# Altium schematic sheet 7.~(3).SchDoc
size 609 x 444 mm
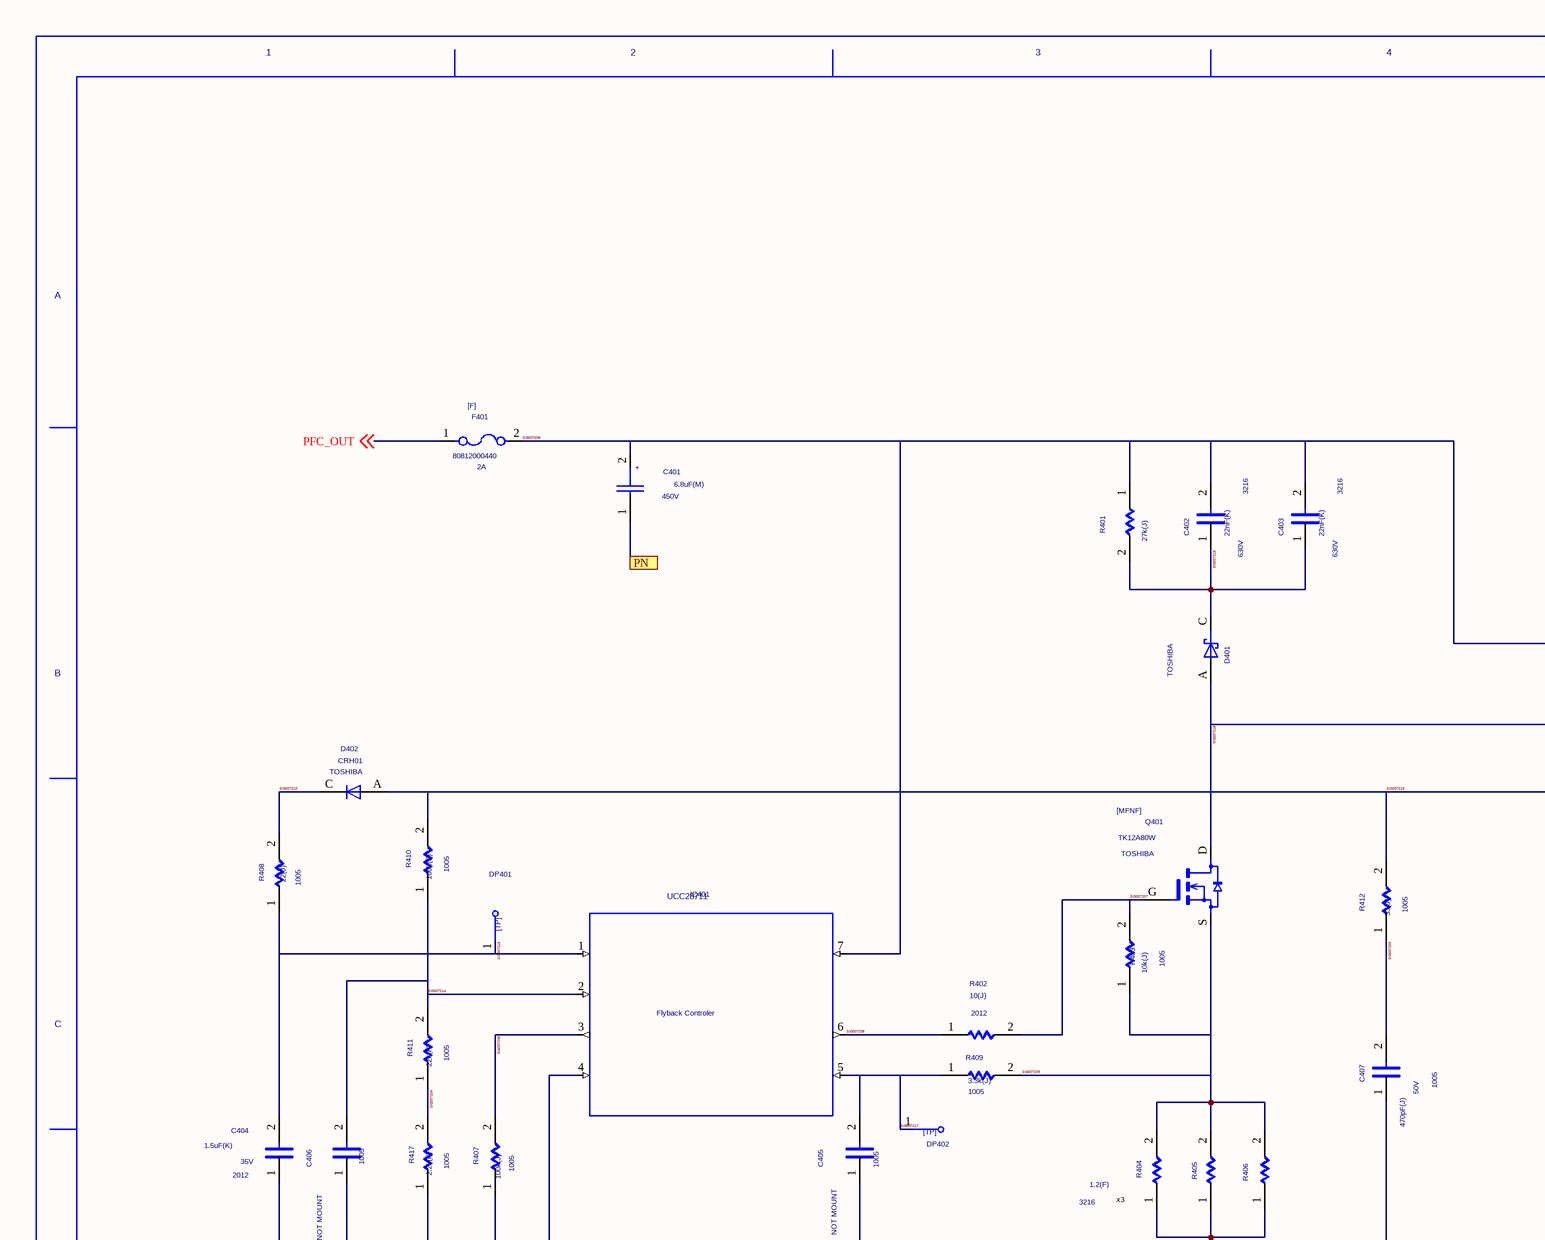
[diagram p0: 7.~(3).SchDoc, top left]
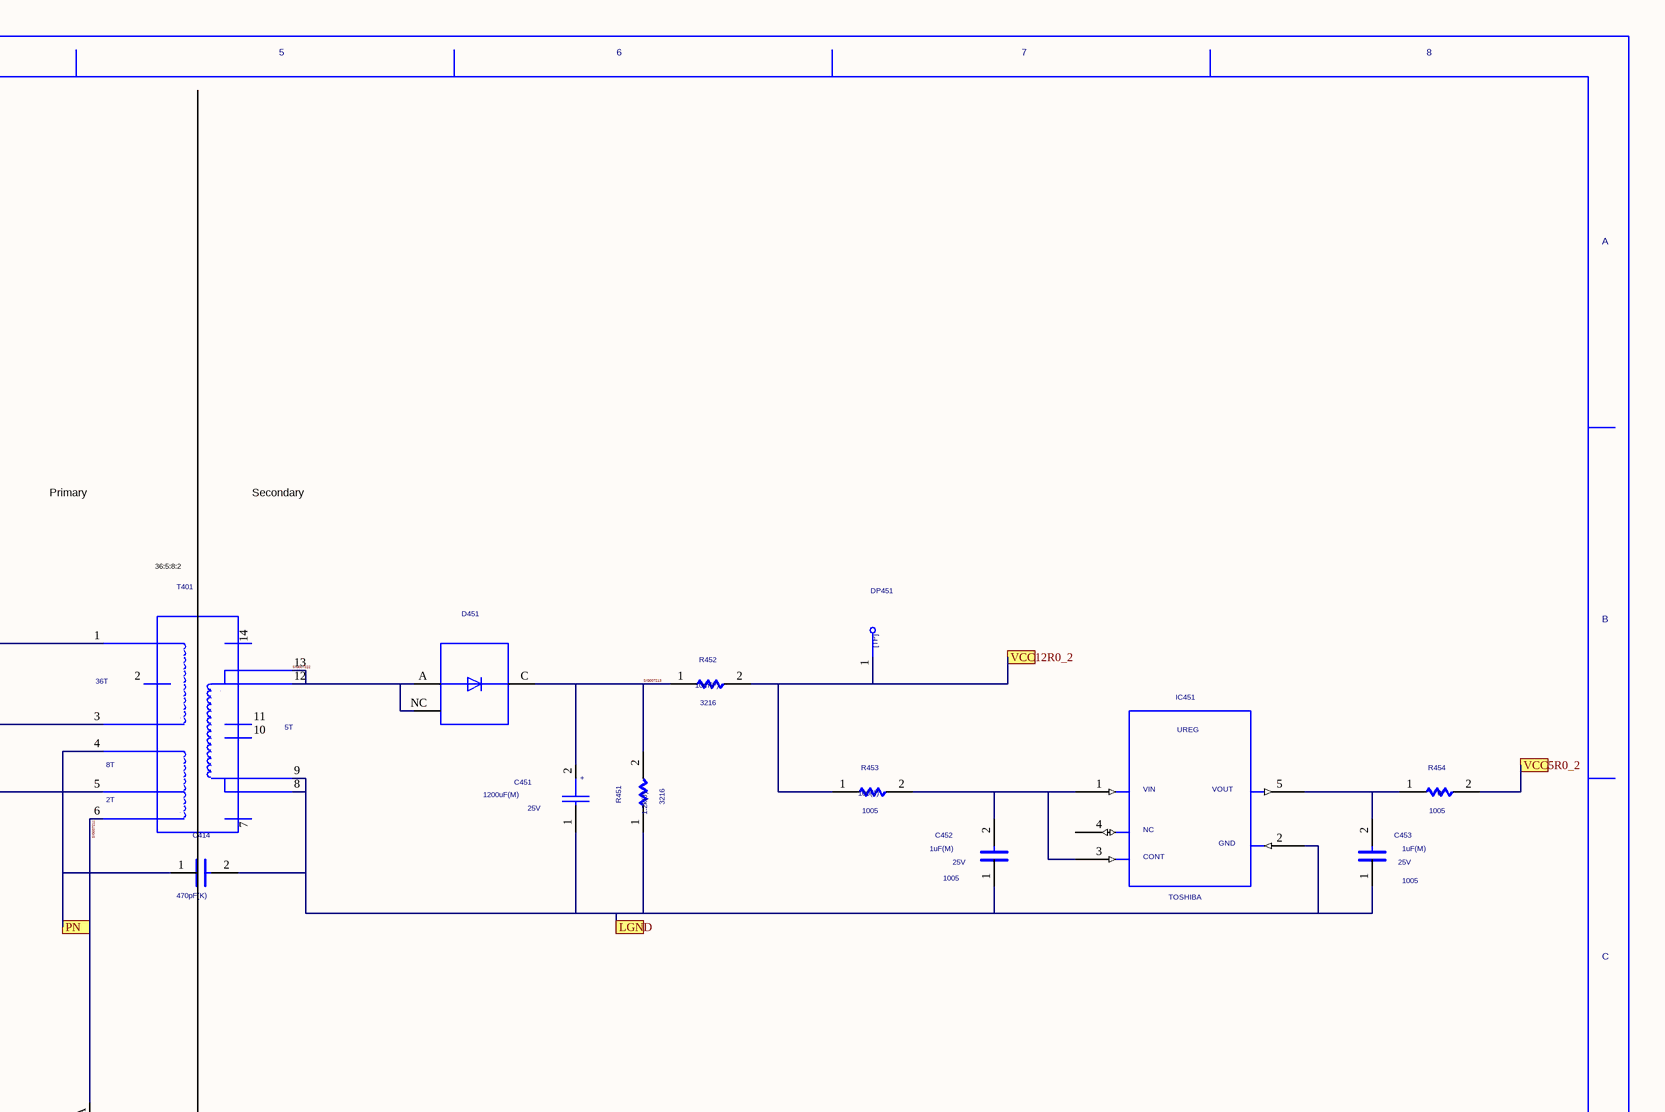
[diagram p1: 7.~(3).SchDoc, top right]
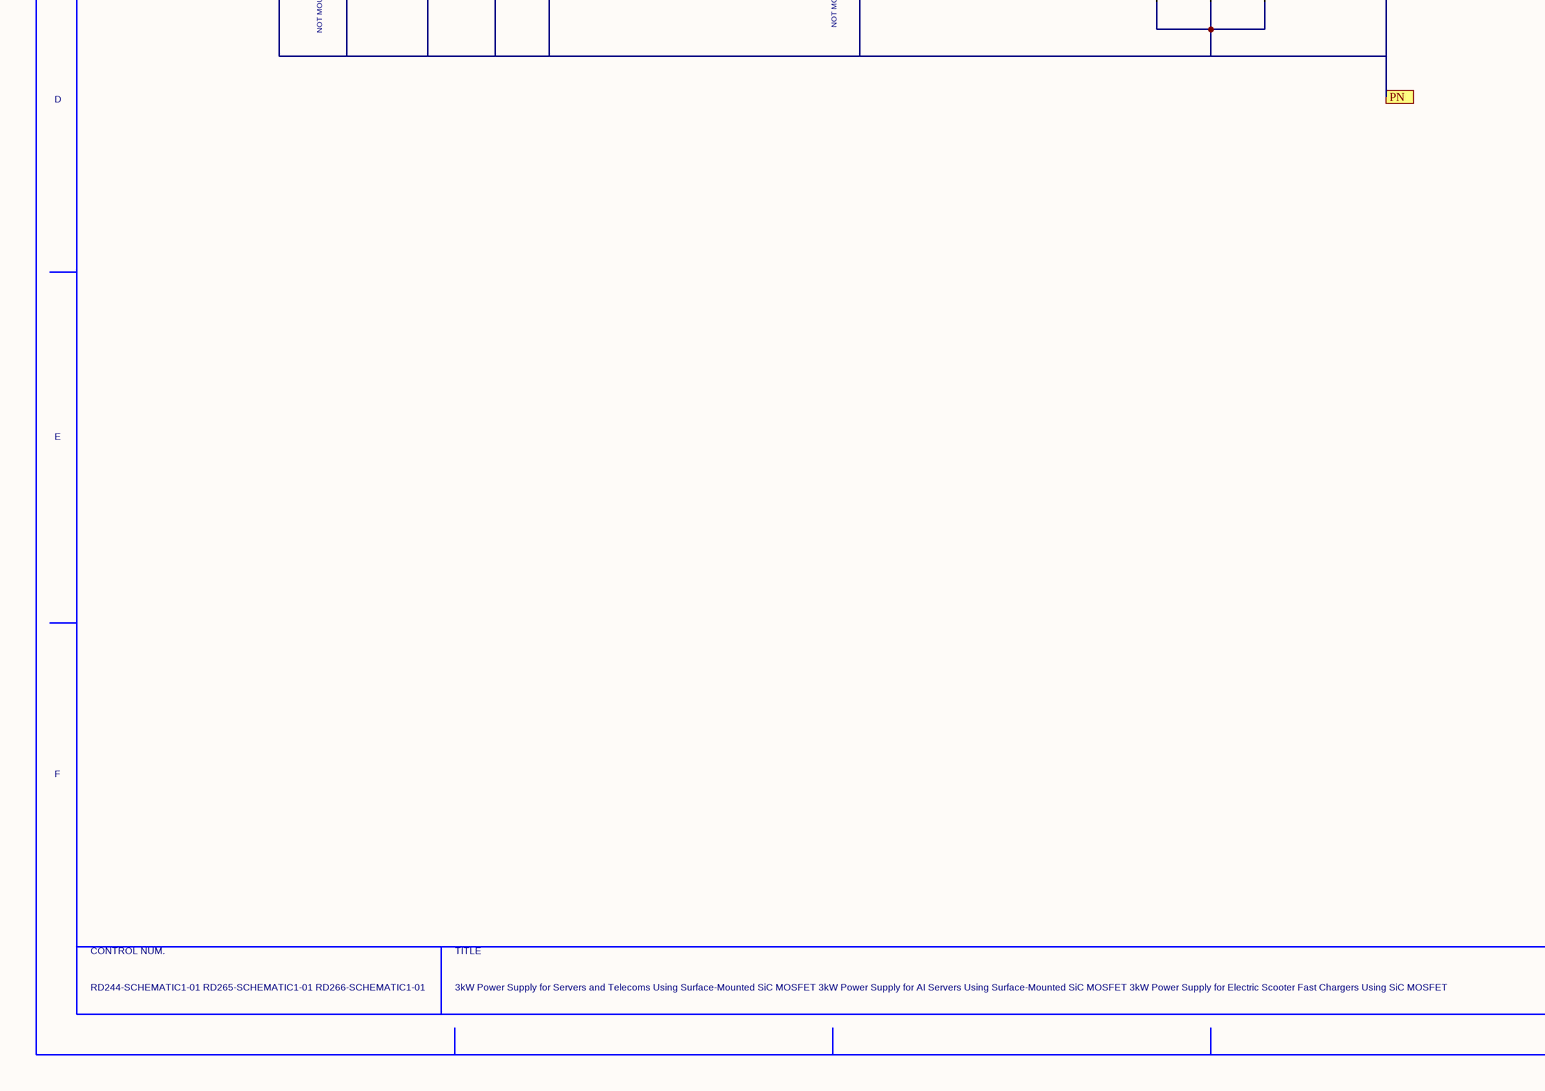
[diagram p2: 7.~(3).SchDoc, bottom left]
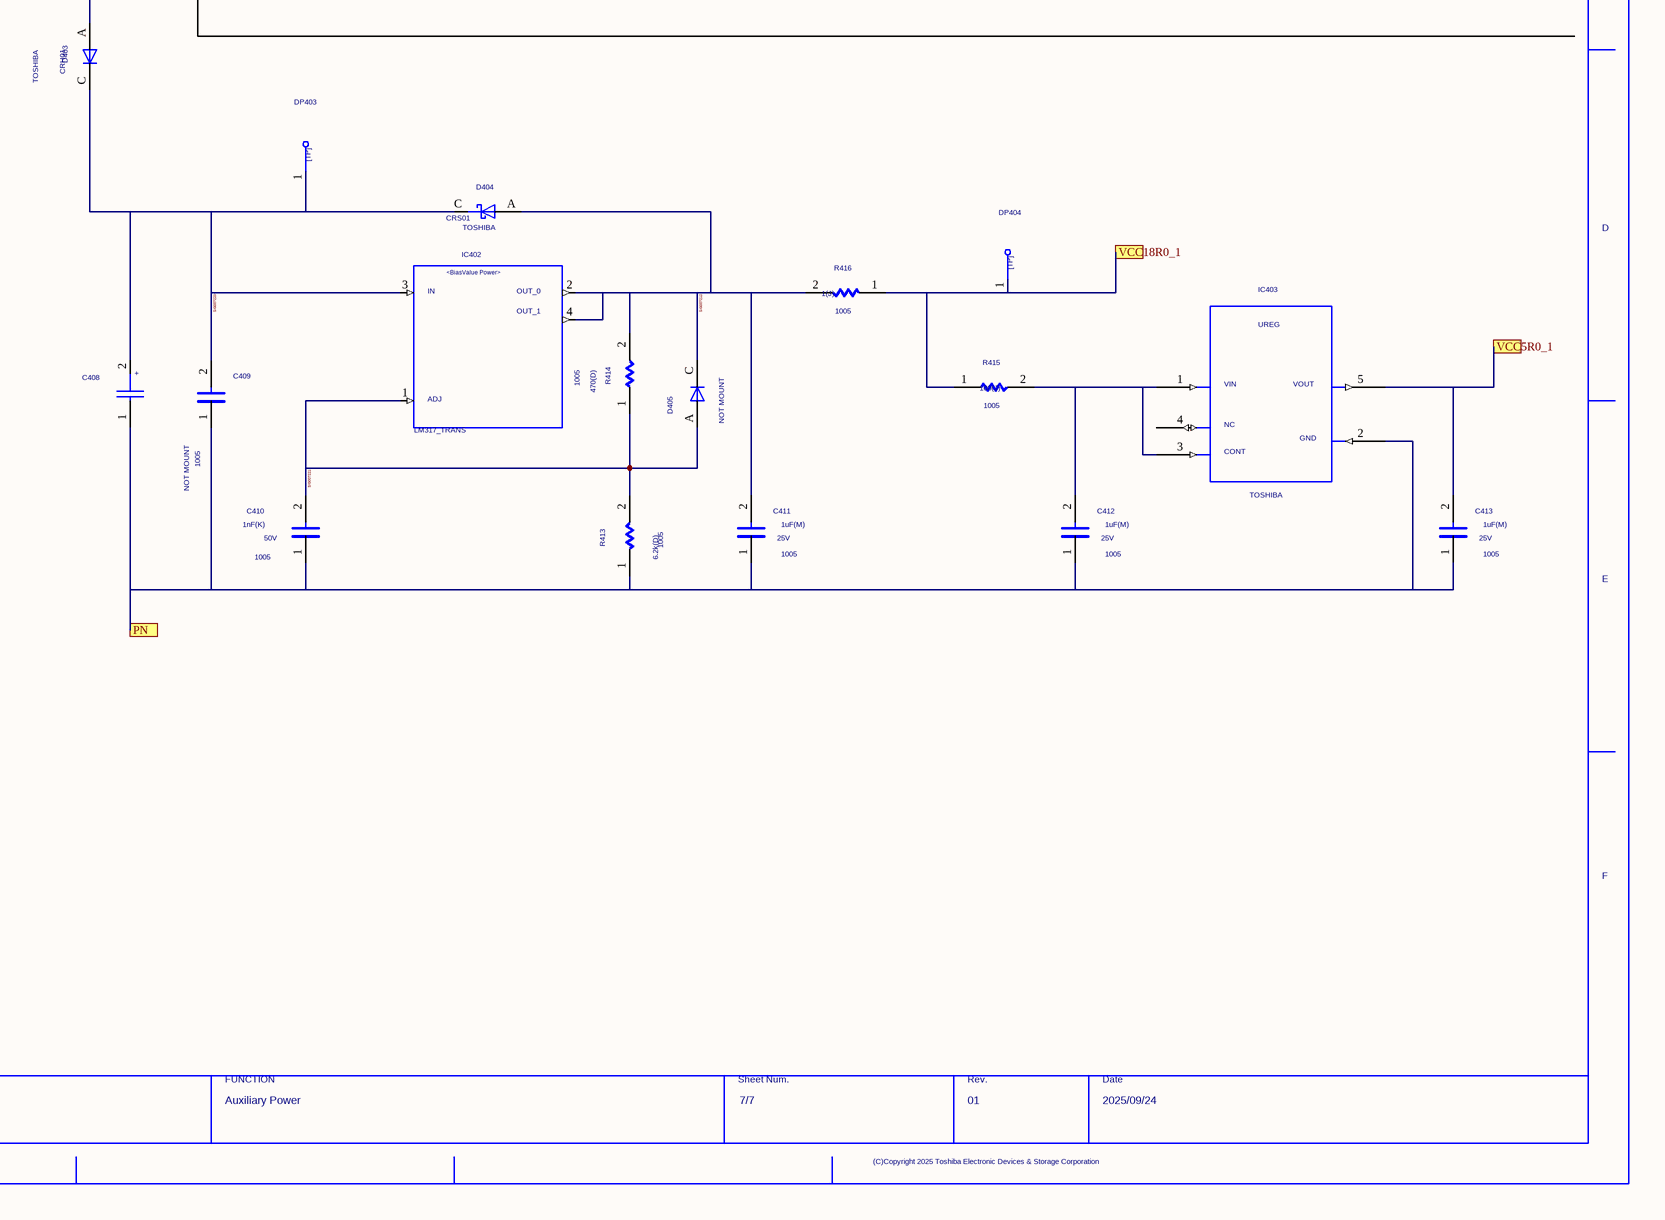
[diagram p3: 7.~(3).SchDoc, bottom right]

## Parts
C401  VAL1: 6.8uF(M)  VAL2: 450V  (hidden comment: CP)
C402  VAL1: 22nF(K)  VAL2: 630V  SIZECODESMD: 3216  (hidden comment: C)
C403  VAL1: 22nF(K)  VAL2: 630V  SIZECODESMD: 3216  (hidden comment: C)
C404  VAL1: 1.5uF(K)  VAL2: 35V  SIZECODESMD: 2012  (hidden comment: GRM21BC71E106KE01)
C405  NOTMOUNT: NOT MOUNT  SIZECODESMD: 1005  (hidden comment: C)
C406  NOTMOUNT: NOT MOUNT  SIZECODESMD: 1005  (hidden comment: C)
C407  VAL1: 470pF(J)  VAL2: 50V  SIZECODESMD: 1005  (hidden comment: C)
C408  EMLA350ARA331MJA0G  (value not drawn)
C409  NOTMOUNT: NOT MOUNT  SIZECODESMD: 1005  (hidden comment: C)
C410  VAL1: 1nF(K)  VAL2: 50V  SIZECODESMD: 1005  (hidden comment: C)
C411  VAL1: 1uF(M)  VAL2: 25V  SIZECODESMD: 1005  (hidden comment: C)
C412  VAL1: 1uF(M)  VAL2: 25V  SIZECODESMD: 1005  (hidden comment: C)
C413  VAL1: 1uF(M)  VAL2: 25V  SIZECODESMD: 1005  (hidden comment: C)
C414  USERCOMPTEXT1: 470pF(K)  (hidden comment: DE2B3SA221KA3BT02F)
C451  VAL1: 1200uF(M)  VAL2: 25V  (hidden comment: CP)
C452  VAL1: 1uF(M)  VAL2: 25V  SIZECODESMD: 1005  (hidden comment: C)
C453  VAL1: 1uF(M)  VAL2: 25V  SIZECODESMD: 1005  (hidden comment: C)
D401  USERCOMPTEXT3: TOSHIBA  (hidden comment: CRF03A)
D402  VAL1: CRH01  USERCOMPTEXT3: TOSHIBA  (hidden comment: D)
D403  VAL1: CRH01  USERCOMPTEXT3: TOSHIBA  (hidden comment: D)
D404  VAL1: CRS01  USERCOMPTEXT3: TOSHIBA  (hidden comment: SBD)
D405  NOTMOUNT: NOT MOUNT  (hidden comment: D)
D451  RF501BGE2S  (value not drawn)
DP401  TP  (value not drawn)
DP402  TP  (value not drawn)
DP403  TP  (value not drawn)
DP404  TP  (value not drawn)
DP451  TP  (value not drawn)
F401  VAL1: 2A  VAL3: 80812000440  (hidden comment: F)
IC401  UCC28711
IC402  LM317_TRANS  [DCY0004A_N]
IC403  USERCOMPTEXT3: TOSHIBA  (hidden comment: TCR1HF50B)
IC451  USERCOMPTEXT3: TOSHIBA  (hidden comment: TCR1HF50B)
Q401  USERCOMPTEXT3: TOSHIBA  VAL3: TK12A80W  (hidden comment: MFNF)
R401  VAL1: 27k(J)  (hidden comment: R)
R402  VAL1: 10(J)  SIZECODESMD: 2012  (hidden comment: R)
R403  VAL1: 10k(J)  SIZECODESMD: 1005  (hidden comment: R)
R404  VAL1: 1.2(F)  SIZECODESMD: 3216  (hidden comment: R)
R405  R  (value not drawn)
R406  R  (value not drawn)
R407  VAL1: 100k(J)  SIZECODESMD: 1005  (hidden comment: R)
R408  VAL1: 22(J)  SIZECODESMD: 1005  (hidden comment: R)
R409  VAL1: 3.3k(J)  SIZECODESMD: 1005  (hidden comment: R)
R410  VAL1: 100k(F)  SIZECODESMD: 1005  (hidden comment: R)
R411  VAL1: 22k(F)  SIZECODESMD: 1005  (hidden comment: R)
R412  VAL1: 33(J)  SIZECODESMD: 1005  (hidden comment: R)
R413  VAL1: 6.2k(D)  SIZECODESMD: 1005  (hidden comment: R)
R414  VAL1: 470(D)  SIZECODESMD: 1005  (hidden comment: R)
R415  VAL1: 100(J)  SIZECODESMD: 1005  (hidden comment: R)
R416  VAL1: 1(J)  SIZECODESMD: 1005  (hidden comment: R)
R417  VAL1: 2.2k(F)  SIZECODESMD: 1005  (hidden comment: R)
R451  VAL1: 1.2k(J)  SIZECODESMD: 3216  (hidden comment: R)
R452  VAL1: 10m(F)  SIZECODESMD: 3216  (hidden comment: R)
R453  VAL1: 100(J)  SIZECODESMD: 1005  (hidden comment: R)
R454  VAL1: 0  SIZECODESMD: 1005  (hidden comment: R)
T401  T3_12V67A  (value not drawn)
U?  DATE: 2025/09/24  DRAWINGNUMBER: RD244-SCHEMATIC1-01 / RD265-SCHEMATIC1-01 / RD266-SCHEMATIC1-01  TITLE: 3kW Power Supply for Servers and Telecoms Using Surface-Mounted SiC MOSFET / 3kW Power Supply for AI Servers Using Surface-Mounted SiC MOSFET / 3kW Power Supply for Electric Scooter Fast Chargers Using SiC MOSFET  FUNCTION: Auxiliary Power  SHEETNUMBER: 7/7  REVISION: 01  (hidden comment: WAKU_DEF_A3_1)

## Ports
LGND, PN, VCC5R0_1, VCC5R0_2, VCC12R0_2, VCC18R0_1

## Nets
LGND: C414.2 C451.1 C452.1 C453.1 IC451.2 R451.1 T401.8 T401.9 ; port LGND
PFC_OUT: F401.1 ; off-sheet PFC_OUT
SIG007201: C453.2 IC451.5 R454.1
SIG007202: C452.2 IC451.1 IC451.3 R453.2
SIG007203: C407.2 R412.1
SIG007204: R411.1 R417.2
SIG007205: IC401.3 R407.2
SIG007206: C401.2 C402.2 C403.2 F401.2 IC401.7 R401.1 T401.1
SIG007207: Q401.G R402.2 R403.2
SIG007208: IC401.6 R402.1
SIG007209: Q401.S R403.1 R404.2 R405.2 R406.2 R409.2
SIG007210: D402.C R408.2
SIG007211: C401.1 C404.1 C405.1 C406.1 C407.1 C408.1 C409.1 C410.1 C411.1 C412.1 C413.1 C414.1 D403.A IC401.4 IC403.2 R404.1 R405.1 R406.1 R407.1 R413.1 R417.1 T401.4 T401.6 ; port PN
SIG007212: C411.2 D404.A D405.C IC402.2 IC402.4 R414.2 R416.2
SIG007213: C451.2 D451.C R451.2 R452.1
SIG007214: C406.2 IC401.2 R410.1 R411.2
SIG007215: C404.2 DP401.1 IC401.1 R408.1
SIG007216: D402.A R410.2 R412.2 T401.5
SIG007217: C405.2 DP402.1 IC401.5 R409.1
SIG007218: D401.A Q401.D T401.3
SIG007219: C402.1 C403.1 D401.C R401.2
SIG007220: C408.2 C409.2 D403.C D404.C DP403.1 IC402.3
SIG007221: C410.2 D405.A IC402.1 R413.2 R414.1
SIG007222: D451.A D451.NC T401.12 T401.13
SIG008125: C412.2 IC403.1 IC403.3 R415.2
VCC5R0_1: C413.2 IC403.5 ; port VCC5R0_1
VCC5R0_2: R454.2 ; port VCC5R0_2
VCC12R0_2: DP451.1 R452.2 R453.1 ; port VCC12R0_2
VCC18R0_1: DP404.1 R415.1 R416.1 ; port VCC18R0_1

Not connected (* = marked no-connect by the designer): IC403 4; IC451 4; T401 2 7 10 11 14

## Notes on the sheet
- Primary
- Secondary
- 36:5:8:2
- (near R404) x3

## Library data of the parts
C401 C451 = CP: SAVEAREA0: -1450,-153,20294,13055; SAVECOUNT: 52; TIME: 15:02:55; UPDATEUSER: fukuda-y; UPDATETIME: 16:13:42; OriginalSymbolOrigin: (2540,10160); SIZECODESMD: DIP; COMP: PRT_3
C402 C403 = C_Dup1: OriginalSymbolOrigin: (2540,7620); COMP: PRT_46; SAVECOUNT: 0
C404 = GRM21BC71E106KE01: TIME: 10:25:11; UPDATEUSER: t4887876; UPDATETIME: 16:23:00; SAVECOUNT: 11; MAKER: Murata; OriginalSymbolOrigin: (2540,7620); CHIPSIZE: 1005; MAXGCOUNT: 1
C405 C406 = C_Dup2: VAL1: 150pF(J); VAL2: 50V; OriginalSymbolOrigin: (2540,7620); COMP: PRT_52; SAVECOUNT: 0
C407 C410 = C_Dup2: OriginalSymbolOrigin: (2540,7620); COMP: PRT_52; SAVECOUNT: 0
C408 = EMLA350ARA331MJA0G: SAVEAREA0: -1450,-153,20294,13055; SAVECOUNT: 53; TIME: 15:02:55; UPDATEUSER: t6860224; UPDATETIME: 18:00:37; VAL1: 330uF(M); VAL2: 35V; OriginalSymbolOrigin: (2540,10160); MAXGCOUNT: 1; SIZECODESMD: 1010
C409 = C_Dup2: VAL1: 2.2nF(K); VAL2: 50V; OriginalSymbolOrigin: (2540,7620); COMP: PRT_52; SAVECOUNT: 0
C411-C413 C452 C453 = C_Dup2: SQ_PART_MODEL: CON_1U; OriginalSymbolOrigin: (2540,7620); COMP: PRT_52; MAXGCOUNT: 1; ADSCNVFLAG: ON; ADSCOMPONENTNAME: C_1608; SAVECOUNT: 0
C414 = DE2B3SA221KA3BT02F: VAL1: 220pF(K); VAL2: 250V; TIME: 18:06:26; UPDATEUSER: t6860224; SAVECOUNT: 1; OriginalSymbolOrigin: (2540,7620); SIZECODESMD: DIP
D401 = CRF03A: SAVEAREA0: -4630,-153,17114,13055; TIME: 14:49:55; UPDATEUSER: t4887876; UPDATETIME: 15:42:51; SAVECOUNT: 12; MAXV: 600V; MAXI: 0.7A; OriginalSymbolOrigin: (5080,5080); USERCOMPTEXT2: 600V,0.7A; MAXGCOUNT: 1
D402 D403 = D: SAVEAREA0: -225,-91,12804,7836; SAVECOUNT: 3; TIME: 14:49:55; UPDATEUSER: 19870035; UPDATETIME: 14:20:16; OriginalSymbolOrigin: (5080,5080); USERCOMPTEXT2: 200V,1A; MAXGCOUNT: 1; ADSCNVFLAG: ON; ADSCOMPONENTNAME: D_D; COMP: GDM420000387
D404 = SBD: SAVEAREA0: -4630,-153,17114,13055; TIME: 14:49:55; UPDATEUSER: fukuda-y; UPDATETIME: 08:16:22; SAVECOUNT: 9; OriginalSymbolOrigin: (5080,5080); USERCOMPTEXT2: 30V,1A; MAXGCOUNT: 1; COMP: K4200730; ADSCNVFLAG: ON; ADSCOMPONENTNAME: D_SBD
D405 = D_Dup1: SAVEAREA0: -225,-91,12804,7836; SAVECOUNT: 3; TIME: 14:49:55; UPDATEUSER: 19870035; UPDATETIME: 14:20:16; OriginalSymbolOrigin: (5080,5080); USERCOMPTEXT2: 100V,0.25A; USERCOMPTEXT3: TOSHIBA; COMP: PRT_26; VAL3: BAS316; MAXGCOUNT: 1
D451 = RF501BGE2S: SAVEAREA0: -4931,-287,27399,20979; TIME: 08:58:08; UPDATEUSER: t4887876; UPDATETIME: 11:52:14; SAVECOUNT: 7; VAL1: 200V; VAL2: 5A; CHIPSET: TO-252GE; OriginalSymbolOrigin: (5080,17780)
DP401-DP404 DP451 = TP: TIME: 16:12:21; UPDATEUSER: fukuda-y; UPDATETIME: 16:18:11; SAVECOUNT: 2; SAVEAREA0: -242,-92,12810,7836; OriginalSymbolOrigin: (0,7620); USERCOMPTEXT1: Φ1.5mm; COMP: DTP815
F401 = F: OriginalSymbolOrigin: (2540,5080); COMP: 808****0440_LF; SAVECOUNT: 0
IC401 = UCC28711DR: PSPICETEMPLATE: X^@REFDES %CS %VS %CBC %DRV %VDD %GND %HV @MODEL; TIME: 16:40:05; UPDATEUSER: t4887876; UPDATETIME: 09:12:44; SAVECOUNT: 14; SAVEAREA0: -40606,-13411,99691,50516; OriginalSymbolOrigin: (2540,38100)
IC402 = LM317MDCY: ALTERNATE PARTNUMBER: LM317DCY; PARTNUMBER: LM317DCYR; MANUFACTURER: Texas Instruments; PIN_COUNT: 4; SYMBOLCREATER: Altium; DEVICESINPACKAGE: 1; ISHETEROGENEOUS: False; DEVICEDESIGNATOR: A; DEVICENUMBERING: Alpha; PSPICETEMPLATE: X^@REFDES %IN %ADJ %OUT_0 %OUT_1 @MODEL; ORIGINALSYMBOLORIGIN: (2540,30480); COMPTYPE: IC; TIME: 16:40:05; UPDATEUSER: t6860224; UPDATETIME: 16:01:55; SAVECOUNT: 6; SAVEAREA0: -16909,0,49982,30480; FUNCTION: FXD
IC403 IC451 = TCR1HF50B: SAVEAREA0: -444,-3509,43701,41525; TIME: 18:31:00; UPDATEUSER: t6860224; UPDATETIME: 18:26:20; SAVECOUNT: 17; VAL1: Linear Regulator; OriginalSymbolOrigin: (7620,35560)
Q401 = MFNF: SAVECOUNT: 11; SAVEAREA0: -7027,-292,21786,15988; OriginalSymbolOrigin: (5080,12700); COMP: K4100860
R401 = R: VAL2: 3W; OriginalSymbolOrigin: (5080,5080); COMP: PRT_54; SIZECODESMD: TH; SAVECOUNT: 0
R402 = R: VAL2: 250mW; OriginalSymbolOrigin: (5080,5080); COMP: R2012; SAVECOUNT: 0
R403 R407 R408 R410-R412 R417 = R: VAL2: 63mW; OriginalSymbolOrigin: (5080,5080); MAXGCOUNT: 1; COMP: GDM010004481; SAVECOUNT: 0
R404 R451 = R: VAL2: 250mW; OriginalSymbolOrigin: (5080,5080); COMP: PRT_5; SAVECOUNT: 0
R405 R406 = R: VAL2: 250mW; VAL1: 1.2(F); OriginalSymbolOrigin: (5080,5080); COMP: PRT_5; SIZECODESMD: 3216; SAVECOUNT: 0
R409 = R: VAL2: 63mW; OriginalSymbolOrigin: (5080,5080); COMP: GDM010004481; SAVECOUNT: 0
R413 R414 = R_Dup2: VAL2: 63mW; OriginalSymbolOrigin: (5080,5080); MAXGCOUNT: 1; COMP: GDM010004481; SAVECOUNT: 0
R415 R453 = R_Dup2: VAL2: 63mW; OriginalSymbolOrigin: (5080,5080); COMP: GDM010004481; CHIPSIZE: 1608; MAXGCOUNT: 1; SAVECOUNT: 0
R416 = R_Dup2: SQ_PART_MODEL: RES_0; VAL2: 63mW; OriginalSymbolOrigin: (5080,5080); COMP: GDM010004481; CHIPSIZE: 1608; MAXGCOUNT: 1; ADSCNVFLAG: ON; ADSCOMPONENTNAME: R_1005; SAVECOUNT: 0
R452 = R: VAL2: 1W; OriginalSymbolOrigin: (5080,5080); COMP: PRT_5; SAVECOUNT: 0
R454 = R_Dup2: SQ_PART_MODEL: RES_0; VAL2: 63mW; OriginalSymbolOrigin: (5080,5080); COMP: GDM010004481; CHIPSIZE: 1608; MAXGCOUNT: 1; ADSCNVFLAG: ON; ADSCOMPONENTNAME: R_1005
T401 = TAM-PQ20-36-5: UPDATEUSER: t4887876; UPDATETIME: 19:22:14; SAVECOUNT: 21; TIME: 16:40:06; SAVEAREA0: -85659,-25353,110804,64166; ORIGINALSYMBOLORIGIN: (0,40640); VAL1: 36:8:2:5
U? = WAKU_DEF_A3_1: PLOTTIME: HH:MM; SAVEAREA0: 96913,-567914,509243,-368858; TIME: 18:12:27; UPDATEUSER: t5459927; UPDATETIME: 13:12:48; SAVECOUNT: 20; ZONEOFFSETX: 36; ZONEOFFSETY: -24; OriginalSymbolOrigin: (12700,-12700); PAGENUMBER: 7; NOTMOUNT: MOUNT; SHTSAVECOUNT: 218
